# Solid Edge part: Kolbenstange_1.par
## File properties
Username: bmolnar
Dokumentum tartalom típus: 0
Author: bmolnar
Last saved by: bmolnar
Revision: 94
Sűrűség: 0,000 kg/m^3
Pontosság: 0,990
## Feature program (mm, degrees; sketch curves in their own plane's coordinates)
base feature "unnamed BaseFeature 1"
thread "unnamed Thread 1"
chamfer "Letörés_1"  SetBackValue2 = 20 deg
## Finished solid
Body 1: solid body, 19 faces, 27 edges, 11 vertices.
  Faces by surface: plane 8, cylinder 5, cone 3, torus 3
  Edges by curve: circle 15, line 7, curve on surface 3, ellipse 2
Bounding box of the edges (mm; curved faces can reach further): 100.000 x 100.000 x 1688.500, from (-50, -50, -86.75) to (50, 50, 1601.75).
Cylindrical faces by radius (mm): R8.75 x1, R10 x1, R12.25 x1, R12.5 x1, R50 x1
Conical faces (half-angle, radius in mm at the cone's reference point): 20 deg R10 x1, 30 deg R12.375 x1, 60 deg R9.375 x1
Toroidal faces (ring radius, tube radius in mm): R9.15 r0.4 x2, R10.45 r1.8 x1
Planar faces by outward normal: +x 1, +z 3, -x 1, -z 1, oblique 2
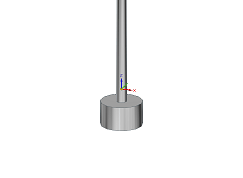
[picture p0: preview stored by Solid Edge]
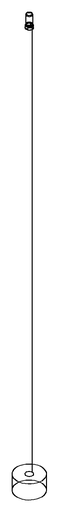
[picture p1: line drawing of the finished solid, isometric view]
